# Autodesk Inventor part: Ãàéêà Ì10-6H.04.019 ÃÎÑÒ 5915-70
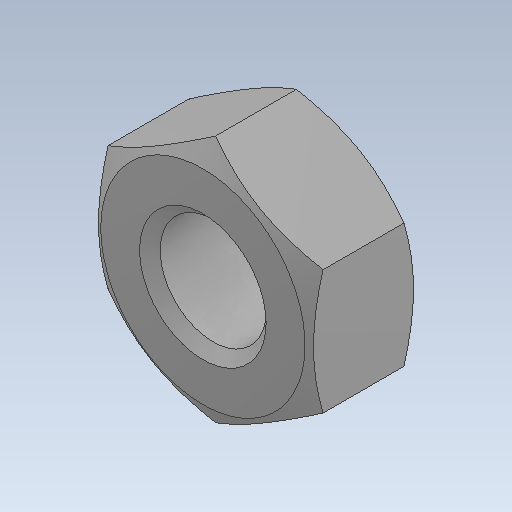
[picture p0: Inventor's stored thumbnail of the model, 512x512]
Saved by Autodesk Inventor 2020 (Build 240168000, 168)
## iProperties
Created: 1900-01
Part Number: Ãàéêà Ì10-6H.04.019 ÃÎÑÒ 5915-70
Material: Générique
Document SubType Name: Modeling
Designer: bruno
Density: 1 g/cm^3
Appearance: Par défaut
Author: bruno
Revision Number: ANYUNSPECIFIED
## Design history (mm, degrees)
feature "Base1"
node "Solide1"
